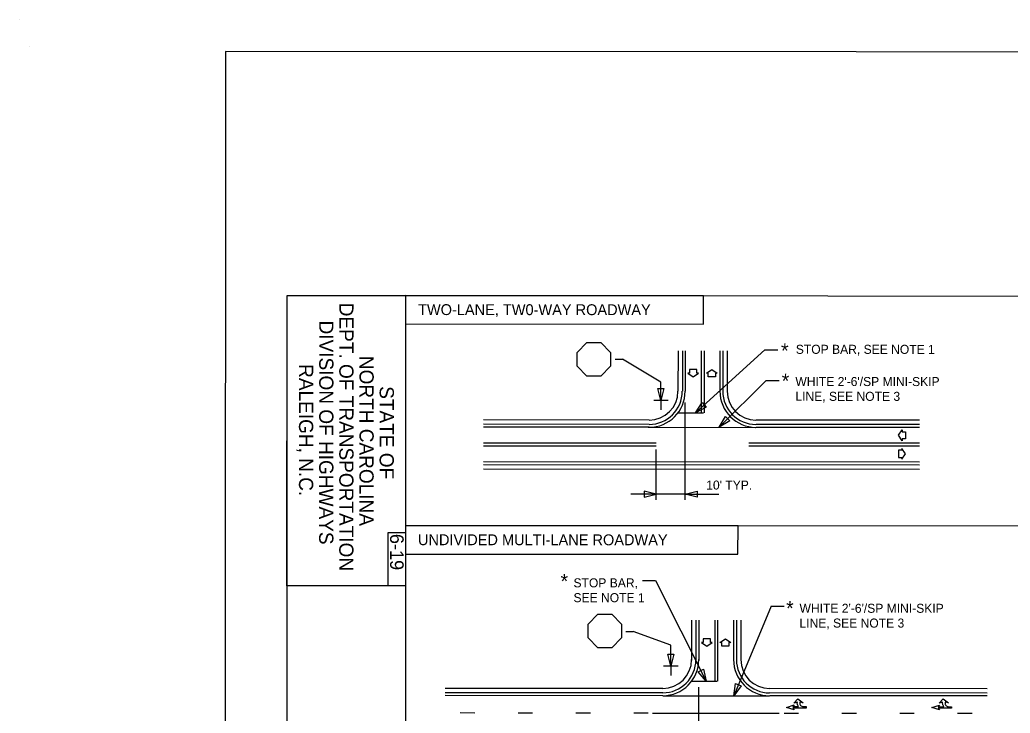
# Model space of a CAD drawing. Extents: x 50667 to 52386, y 46650 to 50479.
# Drawn here: x 50667 to 51455, y 47344 to 47896 of the extents above; entities that cross this region are included whole.
import ezdxf

# ---------------------------------------------------------------- set-up
doc = ezdxf.new("R2010")
doc.units = 0
for name, color, linetype in [('Default', 7, 'Continuous'), ('DEV TUBULAR MARKER SECTIONAL VIEW CELL', 7, 'Continuous'), ('Exist Guardrail Text', 7, 'Continuous'), ('Exist Hydro Spring Text', 7, 'Continuous'), ('Exist Right of Way Monument Text', 7, 'Continuous'), ('Gray Area Fill Shapes', 7, 'Continuous'), ('Matchline', 7, 'Continuous'), ('Prop EOT Dash', 7, 'Continuous'), ('Sheet Sticker Preliminary CELL', 7, 'Continuous'), ('Text', 7, 'Continuous')]:
    doc.layers.add(name, color=color, linetype=linetype)

msp = doc.modelspace()

# ---------------------------------------------------------------- linework, layer by layer
at = {"layer": 'Default'}
for p, q in [((51110.2, 47631.21), (51118.01, 47639.01)), ((51118.01, 47639.01), (51129.08, 47639.01)), ((51129.08, 47639.01), (51136.89, 47631.2)), ((51110.19, 47620.14), (51110.2, 47631.21)), ((51136.89, 47631.2), (51136.88, 47620.13)), ((51204.33, 47583.09), (51259.7, 47633.27)), ((51208.95, 47632.54), (51208.92, 47583.08)), ((51211.25, 47632.53), (51211.22, 47583.08)), ((51259.7, 47633.27), (51270.08, 47633.27)), ((51118, 47612.32), (51110.19, 47620.14)), ((51136.88, 47620.13), (51129.07, 47612.32)), ((51140.57, 47625.83), (51146.32, 47625.82)), ((51176.96, 47607.5), (51146.32, 47625.82)), ((51129.07, 47612.32), (51118, 47612.32)), ((51176.96, 47592.91), (51176.96, 47607.5)), ((51223.23, 47571.64), (51260.57, 47608.91)), ((51260.57, 47608.91), (51270.95, 47608.91)), ((51196.24, 47513.86), (51196.28, 47591.43)), ((51190.52, 47583.09), (51210.94, 47583.08)), ((51224.77, 47573.17), (51223.23, 47571.64)), ((51173.26, 47558.95), (51035.7, 47559.02)), ((51173.26, 47556.65), (51035.7, 47556.72)), ((51382.61, 47558.85), (51246.86, 47558.92)), ((51382.61, 47556.55), (51246.86, 47556.62)), ((51173.24, 47513.88), (51173.26, 47554.02)), ((51173.24, 47518.45), (51152.9, 47518.46)), ((51171.08, 47518.45), (51173.24, 47518.45)), ((51196.24, 47518.44), (51173.24, 47518.45)), ((51198.41, 47518.43), (51196.24, 47518.44)), ((51196.24, 47518.44), (51223.05, 47518.42)), ((52075.53, 47492.74), (50973.75, 47493.26)), ((51162.37, 47449.59), (51172.75, 47449.58)), ((51172.75, 47449.58), (51213.07, 47369.5)), ((51119.02, 47415.01), (51126.83, 47422.82)), ((51126.83, 47422.82), (51137.85, 47422.81)), ((51137.85, 47422.81), (51145.61, 47415)), ((51264.75, 47429.36), (51234.83, 47357.99)), ((51264.75, 47429.36), (51275.13, 47429.36)), ((51119.01, 47403.99), (51119.02, 47415.01)), ((51145.61, 47415), (51145.61, 47403.98)), ((51219.77, 47418.25), (51219.75, 47369.53)), ((51222.07, 47418.25), (51222.05, 47369.53)), ((51149.06, 47409.2), (51154.81, 47409.2)), ((51184.9, 47398.24), (51154.81, 47409.2)), ((51126.82, 47396.13), (51119.01, 47403.99)), ((51145.61, 47403.98), (51137.84, 47396.12)), ((51184.89, 47381.56), (51184.9, 47398.24)), ((51137.84, 47396.12), (51126.82, 47396.13)), ((51201.38, 47369.51), (51221.79, 47369.5)), ((51212.1, 47371.44), (51213.07, 47369.5)), ((51178.37, 47363.77), (51005.25, 47363.85)), ((51178.37, 47360.32), (51005.25, 47360.4)), ((51207.05, 47265.47), (51207.09, 47364.89)), ((51436.59, 47363.65), (51263.47, 47363.73)), ((51436.59, 47360.2), (51263.47, 47360.28)), ((51178.37, 47358.02), (51005.25, 47358.1)), ((51436.59, 47357.9), (51263.47, 47357.98))]:
    msp.add_line(p, q, dxfattribs=at)
for points in [[(51028.82, 47344.29), (51017.32, 47344.3)], [(51074.82, 47344.27), (51063.32, 47344.27)], [(51120.87, 47344.25), (51109.37, 47344.25)], [(51166.87, 47344.23), (51155.37, 47344.23)], [(51274.96, 47344.18), (51286.46, 47344.17)], [(51320.96, 47344.15), (51332.46, 47344.15)], [(51366.96, 47344.18), (51378.46, 47344.18)], [(51412.96, 47344.16), (51424.46, 47344.15)]]:
    msp.add_lwpolyline(points, dxfattribs=at)
for centre, radius, start, end in [((51178.36, 47386.79), 26.45, 269.97341, 359.97341), ((51178.36, 47386.79), 23, 269.97341, 359.97341), ((51178.36, 47386.79), 28.75, 269.97341, 359.97341), ((51263.46, 47386.75), 28.75, 179.97341, 269.97341), ((51263.46, 47386.75), 26.45, 179.97341, 269.97341), ((51263.46, 47386.75), 23, 179.97341, 269.97341)]:
    msp.add_arc(centre, radius, start, end, dxfattribs=at)
at = {"layer": 'DEV TUBULAR MARKER SECTIONAL VIEW CELL'}
for points in [[(50879.23, 46906.71), (50879.58, 47676.39), (52169.91, 47675.79), (52169.55, 46906.11)], [(50973.82, 47653.82), (51210.89, 47653.71), (51210.9, 47676.23), (50973.83, 47676.34)], [(50973.74, 47470.73), (51238.27, 47470.61), (51238.28, 47493.13), (50973.75, 47493.26)]]:
    msp.add_lwpolyline(points, close=True, dxfattribs=at)
at = {"layer": 'Exist Guardrail Text'}
for p, q in [((51182.83, 47592.91), (51171.18, 47592.91)), ((51176.96, 47592.91), (51176.95, 47585.37)), ((51190.76, 47381.56), (51179.12, 47381.56)), ((51184.89, 47381.56), (51184.89, 47374.02))]:
    msp.add_line(p, q, dxfattribs=at)
at = {"layer": 'Exist Hydro Spring Text'}
for p, q in [((51166.89, 47571.6), (51251.99, 47571.57)), ((51178.35, 47358.04), (51263.45, 47358)), ((51170.37, 47344.19), (51271.12, 47344.14))]:
    msp.add_line(p, q, dxfattribs=at)
at = {"layer": 'Exist Right of Way Monument Text'}
for p, q in [((50666.84, 47895.8), (50666.84, 47895.8)), ((50674.32, 47874.63), (50674.32, 47874.63)), ((50831.4, 47870.6), (50831.4, 47870.6))]:
    msp.add_line(p, q, dxfattribs=at)
msp.add_lwpolyline([(52335.61, 47869.9), (50830.4, 47870.6), (50829.91, 46815.38), (52335.12, 46814.68)], close=True, dxfattribs=at)
at = {"layer": 'Gray Area Fill Shapes'}
for p, q in [((51190.55, 47632.54), (51190.53, 47600.34)), ((51194, 47632.54), (51193.98, 47600.34)), ((51196.3, 47632.54), (51196.28, 47600.34)), ((51223.9, 47632.53), (51223.88, 47600.33)), ((51226.2, 47632.53), (51226.18, 47600.33)), ((51229.65, 47632.53), (51229.63, 47600.33)), ((51167.52, 47573.9), (51035.7, 47573.97)), ((51167.52, 47571.6), (51035.7, 47571.67)), ((51167.52, 47577.35), (51035.71, 47577.42)), ((51382.62, 47577.25), (51252.62, 47577.31)), ((51382.62, 47573.8), (51252.62, 47573.86)), ((51382.61, 47571.5), (51252.62, 47571.56)), ((51382.6, 47543.9), (51035.69, 47544.07)), ((51382.6, 47541.6), (51035.69, 47541.77)), ((51382.6, 47538.15), (51035.69, 47538.32)), ((51201.37, 47418.26), (51201.35, 47386.06)), ((51204.82, 47418.26), (51204.8, 47386.05)), ((51207.12, 47418.25), (51207.1, 47386.05)), ((51234.72, 47418.24), (51234.7, 47386.04)), ((51237.02, 47418.24), (51237, 47386.04)), ((51240.47, 47418.24), (51240.45, 47386.04))]:
    msp.add_line(p, q, dxfattribs=at)
for points in [[(51199.78, 47617.62), (51199.78, 47614.75), (51198.34, 47614.75), (51202.7, 47611.87), (51206.97, 47614.74), (51205.53, 47614.74), (51205.53, 47617.62)], [(51214.52, 47611.83), (51214.52, 47614.71), (51213.09, 47614.71), (51217.45, 47617.58), (51221.71, 47614.7), (51220.27, 47614.7), (51220.27, 47611.83)], [(51371.63, 47562.32), (51368.76, 47562.32), (51368.76, 47560.89), (51365.89, 47565.25), (51368.76, 47569.51), (51368.76, 47568.07), (51371.64, 47568.07)], [(51365.84, 47547.56), (51368.72, 47547.56), (51368.72, 47546.12), (51371.59, 47550.48), (51368.72, 47554.74), (51368.72, 47553.31), (51365.84, 47553.31)], [(51210.6, 47403.34), (51210.6, 47400.46), (51209.16, 47400.46), (51213.52, 47397.58), (51217.79, 47400.46), (51216.35, 47400.46), (51216.35, 47403.33)], [(51225.34, 47397.54), (51225.35, 47400.42), (51223.91, 47400.42), (51228.27, 47403.29), (51232.53, 47400.42), (51231.1, 47400.42), (51231.09, 47397.54)]]:
    msp.add_lwpolyline(points, close=True, dxfattribs=at)
for centre, radius, start, end in [((51167.5, 47600.35), 26.45, 269.97341, 359.97341), ((51167.5, 47600.35), 23, 269.97341, 359.97341), ((51167.5, 47600.35), 28.75, 269.97341, 359.97341), ((51252.6, 47600.31), 28.75, 179.97341, 269.97341), ((51252.6, 47600.31), 26.45, 179.97341, 269.97341), ((51252.6, 47600.31), 23, 179.97341, 269.97341)]:
    msp.add_arc(centre, radius, start, end, dxfattribs=at)
at = {"layer": 'Matchline'}
for points in [[(51292.64, 47348.11), (51281.84, 47348.11), (51283.09, 47346.76), (51276.76, 47348.74), (51283.09, 47350.71), (51281.84, 47349.36), (51286.54, 47349.36), (51286.09, 47349.93), (51285.83, 47350.37), (51285.63, 47350.93), (51285.53, 47351.38), (51285.45, 47351.96), (51285.48, 47352.99), (51282.67, 47352.16), (51285.89, 47355.69), (51290.25, 47352.37), (51287.45, 47352.99), (51287.46, 47352.18), (51287.49, 47351.7), (51287.6, 47351.22), (51287.82, 47350.8), (51288.06, 47350.38), (51288.5, 47349.97), (51289.04, 47349.65), (51289.62, 47349.45), (51290.28, 47349.35), (51292.64, 47349.35)], [(51292.64, 47348.11), (51281.84, 47348.11), (51283.09, 47346.76), (51276.76, 47348.74), (51283.09, 47350.71), (51281.84, 47349.36), (51286.54, 47349.36), (51286.09, 47349.93), (51285.83, 47350.37), (51285.63, 47350.93), (51285.53, 47351.38), (51285.45, 47351.96), (51285.48, 47352.99), (51282.67, 47352.16), (51285.89, 47355.69), (51290.25, 47352.37), (51287.45, 47352.99), (51287.46, 47352.18), (51287.49, 47351.7), (51287.6, 47351.22), (51287.82, 47350.8), (51288.06, 47350.38), (51288.5, 47349.97), (51289.04, 47349.65), (51289.62, 47349.45), (51290.28, 47349.35), (51292.64, 47349.35)], [(51408.26, 47348.05), (51397.47, 47348.06), (51398.71, 47346.71), (51392.38, 47348.68), (51398.71, 47350.65), (51397.47, 47349.31), (51402.17, 47349.3), (51401.71, 47349.87), (51401.45, 47350.31), (51401.25, 47350.87), (51401.15, 47351.33), (51401.07, 47351.91), (51401.1, 47352.94), (51398.3, 47352.11), (51401.52, 47355.64), (51405.88, 47352.31), (51403.07, 47352.94), (51403.09, 47352.13), (51403.11, 47351.65), (51403.23, 47351.17), (51403.45, 47350.75), (51403.69, 47350.33), (51404.13, 47349.91), (51404.66, 47349.59), (51405.24, 47349.39), (51405.9, 47349.29), (51408.26, 47349.3)], [(51408.26, 47348.05), (51397.47, 47348.06), (51398.71, 47346.71), (51392.38, 47348.68), (51398.71, 47350.65), (51397.47, 47349.31), (51402.17, 47349.3), (51401.71, 47349.87), (51401.45, 47350.31), (51401.25, 47350.87), (51401.15, 47351.33), (51401.07, 47351.91), (51401.1, 47352.94), (51398.3, 47352.11), (51401.52, 47355.64), (51405.88, 47352.31), (51403.07, 47352.94), (51403.09, 47352.13), (51403.11, 47351.65), (51403.23, 47351.17), (51403.45, 47350.75), (51403.69, 47350.33), (51404.13, 47349.91), (51404.66, 47349.59), (51405.24, 47349.39), (51405.9, 47349.29), (51408.26, 47349.3)]]:
    msp.add_lwpolyline(points, close=True, dxfattribs=at)
at = {"layer": 'Prop EOT Dash'}
for points in [[(51179.33, 47602.4), (51176.96, 47592.91), (51174.59, 47602.4)], [(51179.33, 47602.4), (51176.96, 47592.91), (51174.59, 47602.4)], [(51212.95, 47587.7), (51204.33, 47583.09), (51209.76, 47591.22)], [(51212.95, 47587.7), (51204.33, 47583.09), (51209.76, 47591.22)], [(51231.71, 47576.7), (51223.23, 47571.64), (51228.33, 47580.1)], [(51231.71, 47576.7), (51223.23, 47571.64), (51228.33, 47580.1)], [(51163.66, 47516.05), (51173.24, 47518.45), (51163.66, 47520.85)], [(51163.66, 47516.05), (51173.24, 47518.45), (51163.66, 47520.85)], [(51205.83, 47516.03), (51196.24, 47518.44), (51205.83, 47520.83)], [(51205.83, 47516.03), (51196.24, 47518.44), (51205.83, 47520.83)], [(51187.27, 47391.05), (51184.89, 47381.56), (51182.52, 47391.05)], [(51187.27, 47391.05), (51184.89, 47381.56), (51182.52, 47391.05)], [(51210.91, 47379.14), (51213.07, 47369.5), (51206.63, 47377)], [(51210.91, 47379.14), (51213.07, 47369.5), (51206.63, 47377)], [(51240.72, 47365.92), (51234.83, 47357.99), (51236.3, 47367.76)], [(51240.72, 47365.92), (51234.83, 47357.99), (51236.3, 47367.76)]]:
    msp.add_lwpolyline(points, close=True, dxfattribs=at)
at = {"layer": 'Sheet Sticker Preliminary CELL'}
msp.add_lwpolyline([(50973.73, 47445.44), (50879.43, 47445.48), (50879.54, 47676.39), (50973.83, 47676.34), (50973.48, 46906.67), (50879.18, 46906.71), (50879.19, 46930.29), (50973.49, 46930.24), (50973.5, 46944.38), (50879.2, 46944.42)], dxfattribs=at)
at = {"layer": 'Text'}
msp.add_lwpolyline([(50960, 47487.8), (50973.75, 47487.79), (50973.73, 47445.44), (50959.98, 47445.44)], close=True, dxfattribs=at)

# ---------------------------------------------------------------- texts
at = {"layer": 'Default'}
for s, height, p in [('TWO-LANE, TW0-WAY ROADWAY', 8.652, (50983.72, 47660.9)), ('*', 11.5, (51272.54, 47626.78)), ('STOP BAR, SEE NOTE 1', 7.1874, (51284.27, 47630.06)), ('*', 11.5, (51273.09, 47602.77)), ("WHITE 2'-6'/SP MINI-SKIP ", 7.1874, (51283.93, 47604.45)), ('LINE, SEE NOTE 3', 7.1874, (51283.93, 47592.66)), ("10' TYP.", 7.187, (51213, 47522.07)), ('UNDIVIDED MULTI-LANE ROADWAY', 8.652, (50983.63, 47477.82)), ('*', 11.5, (51097.13, 47443.42)), ('STOP BAR,', 7.187, (51107.38, 47444.25)), ('SEE NOTE 1', 7.187, (51107.38, 47432.47)), ('*', 11.5, (51276.59, 47421.83)), ("WHITE 2'-6'/SP MINI-SKIP ", 7.1874, (51287.21, 47424.05)), ('LINE, SEE NOTE 3', 7.1874, (51287.2, 47412.27))]:
    msp.add_text(s, height=height, rotation=359.97341, dxfattribs=at).set_placement(p)
at = {"layer": 'Sheet Sticker Preliminary CELL'}
for s, p in [('DEPT. OF TRANSPORTATION', (50921.08, 47670.71)), ('DIVISION OF HIGHWAYS', (50905.07, 47656.54)), ('NORTH CAROLINA', (50937.11, 47628.44)), ('RALEIGH, N.C.', (50889, 47621.85)), ('STATE OF ', (50953.15, 47604.29))]:
    msp.add_text(s, height=11.315, rotation=269.97341, dxfattribs=at).set_placement(p)
at = {"layer": 'Text'}
msp.add_text('6-19', height=10.781, rotation=269.97341, dxfattribs=at).set_placement((50961.48, 47486.8))

doc.saveas('drawing.dxf')
